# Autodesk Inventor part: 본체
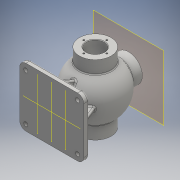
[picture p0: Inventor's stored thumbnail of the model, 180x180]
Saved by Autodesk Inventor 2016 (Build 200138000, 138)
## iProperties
Created: 2017-01
Part Number: 본체
Material: 일반
Document SubType Name: Modeling
Designer: Administrator
Density: 1 g/cm^3
Appearance: 기본값
Author: Administrator
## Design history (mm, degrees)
sketch "스케치1"
  geometry: L1 (0, 0)-(125, 0); L2 (125, 0)-(125, -115); L3 (125, -115)-(0, -115); L4 (0, -115)-(0, 0)
  constraints: 8 end point, 2 parallel, 1 horizontal, 1 perpendicular
  dimensions: "d0" = 115 distance of L1.end L2.end; "d1" = 125 distance of L2.end L3.end
extrude "돌출1" new body sketch "스케치1" distance "d2" = 10; taper "d3" = 0 deg
sketch "스케치2"
  geometry: L1 (-125, 0)-(-125, 115) reference; L2 (-125, 0)-(0, 0) reference; 1 further point
  dimensions: "d4" = 12 distance from line of L1 point (-113, 12); "d5" = 12 distance from line of L2 point (-113, 12)
hole "구멍1" sketch "스케치2" at (-113, 12) diameter "d6" = 8; stored, may be unused: countersink angle "d10" = 90 deg, drill point angle "d12" = 118 deg; dims "d7" = 6, "d8" = 12, "d9" = 3, "d11" = 8
fillet "모깎기1" dims "d19" = 12
node "작업 평면1"
sketch "스케치3"
  geometry: L1 (113.5, 116)-(113.5, 102.5); L2 (113.5, 85)-(-22.5, 85); L3 (-22.5, 102.5)-(-22.5, 116); L4 (91, 0)-(0, 0) reference; L5 (-12, 10)-(-12, 0) reference; L6 (-22.5, 116)-(2.512, 116); L7 (88.488, 116)-(113.5, 116); L8 (-6.5, 102.5)-(6.222, 102.5); L9 (-6.5, 102.5)-(-22.5, 102.5); L10 (113.5, 102.5)-(97.5, 102.5); L11 (97.5, 102.5)-(97.5, 103.5); L12 (97.5, 103.5)-(95.75, 103.5); L13 (95.75, 103.5)-(95.75, 102.5); L14 (95.75, 102.5)-(84.778, 102.5); A1 r 53 centre (45.5, 85) between (88.488, 116) and (2.512, 116); A2 r 43 centre (45.5, 85) between (84.778, 102.5) and (6.222, 102.5); 2 further points
  constraints: 24 end point, 7 perpendicular, 4 point on circle, 3 parallel, 2 centre point, 2 horizontal, 2 point on line, 1 midpoint, 1 vertical
  dimensions: "d22" = 136 distance of L3.end L1.start; "d23" = 85 distance between parallel lines of L4 L2; "d24" = 31 distance of L2.end L3.end; "d25" = 10.5 distance between parallel lines of L5 L3; "d26" = 53 radius of A1; "d28" = 43 radius of A2; "d36" = 17.5 distance between parallel lines of L2 L8; "d39" = 16 distance of L1.end L10.end; "d40" = 18.5 distance between parallel lines of L2 L12; "d41" = 17.5 distance between parallel lines of L2 L14; "d42" = 17.5 distance between parallel lines of L2 L10; "d43" = 1.75 distance of L11.end L12.end; "d44" = 136 distance between parallel lines of L3 L1; "d45" = 31 distance between parallel lines of L2 L6; "d46" = 68 distance of L2.end A1.centre
revolve "회전1" sketch "스케치3" stored, may be unused: angle "d32" = 90 deg
fillet "모깎기2" dims "d47" = 3
chamfer "모따기1" distance "d48" = 1; stored, may be unused: second distance "d49" = 2, angle "d50" = 45 deg
node "작업 평면2"
sketch "스케치4"
  geometry: L1 (-93.5, -125.5)-(-31.5, -125.5) reference; L2 (-125, -103)-(-125, -12) reference; C1 r 27 at (-62.5, -57.5); 1 further point
  constraints: 1 centre point
  dimensions: "d52" = 68 distance from line of C1.centre L1; "d53" = 62.5 distance from line of L2 C1.centre; "d54" = 54 diameter of C1
extrude "돌출2" join sketch "스케치4" stored distance "d55" = 10; taper "d56" = 0 deg
sketch "스케치5"
  geometry: C1 r 13 at (0, 0); 1 further point
  constraints: 1 centre point
  dimensions: "d57" = 26 diameter of C1
extrude "돌출3" cut sketch "스케치5" distance "d58" = 58; taper "d59" = 0 deg
fillet "모깎기3" dims "d60" = 3
chamfer "모따기2" distance "d61" = 1; stored, may be unused: second distance "d62" = 2, angle "d63" = 45 deg
sketch "스케치6" dims "d64" = 40
  geometry: 3 further points
  constraints: 1 horizontal alignment, 2 other
hole "구멍2" sketch "스케치6" at (-20, 0) diameter "d65" = 3.242; stored, may be unused: countersink angle "d69" = 90 deg, drill point angle "d71" = 118 deg; dims "d66" = 9, "d67" = 12, "d68" = 3, "d70" = 11
sketch "스케치7" dims "d75" = 48
  geometry: 3 further points
  constraints: 1 vertical alignment, 2 other
hole "구멍3" sketch "스케치7" at (0, 24) diameter "d76" = 3.242; stored, may be unused: countersink angle "d80" = 90 deg, drill point angle "d82" = 118 deg; dims "d77" = 16, "d78" = 12, "d79" = 3, "d81" = 19
sketch "스케치8" dims "d86" = 45
  geometry: 3 further points
  constraints: 1 vertical alignment, 2 other
hole "구멍4" sketch "스케치8" at (0, 22.5) diameter "d87" = 3.242; stored, may be unused: countersink angle "d91" = 90 deg, drill point angle "d93" = 118 deg; dims "d88" = 12, "d89" = 12, "d90" = 3, "d92" = 15
node "작업 평면3"
sketch "스케치11"
  geometry: L1 (101, 10)-(110, 10) reference; L2 (103, 10)-(86.485, 50.876); L3 (103, 10)-(-2, 10); L4 (101, 10)-(0, 10) reference; L5 (14.515, 50.876)-(-2, 10); L6 (-9, 10)-(0, 10) reference; L7 (113, 0)-(113, 7) reference; L8 (-12, 7)-(-12, 0) reference; A1 r 49.592 centre (50.5, 85) between (14.515, 50.876) and (86.485, 50.876)
  constraints: 6 end point, 2 point on circle, 2 point on line, 1 centre point
  dimensions: "d114" = 112 deg angle of L1 L2; "d115" = 112 deg angle of L6 L5; "d116" = 10 distance from line of L7 L2.start; "d117" = 10 distance from line of L8 L3.end
extrude "돌출5" join sketch "스케치11" stored distance "d118" = 8; taper "d119" = 0 deg
sketch "스케치12"
  geometry: L1 (79.219, 44.109)-(93, 10); L2 (91, 10)-(100, 10) reference; L3 (103, 7)-(103, 0) reference; A1 r 53 centre (45.5, 85) between (87.613, 117.179) and (87.613, 52.821) reference; 1 further point
  constraints: 2 end point, 1 point on circle
  dimensions: "d120" = 112 deg angle of L2 L1; "d121" = 0 distance from line of L2 L1.end; "d122" = 10 distance from line of L3 L1.end
feature "리브2" sketch "스케치12" dims "d123" = 1, "d124" = 8, "d125" = 0, "d126" = 0, "d127" = 1, "d128" = 1
fillet "모깎기4" dims "d129" = 3
fillet "모깎기5" dims "d130" = 3
node "작업 평면4"
node "작업 평면5"
sketch "스케치16"
  geometry: L1 (-145.589, -62.485)-(-145.589, -28.515); L2 (-145.589, -28.515)-(-134.411, -28.515); L3 (-134.411, -28.515)-(-134.411, -62.485); L4 (-134.411, -62.485)-(-145.589, -62.485); L5 (-150, -67.121)-(-150, -63.879) reference; L6 (-116, 22.5)-(-54, 22.5) reference; 3 further points
  constraints: 2 midpoint, 2 other
  dimensions: "d139" = 10 distance from line of L5 point (-140, -62.485); "d140" = 68 distance from line of L6 point (-145.589, -45.5)
feature "엠보싱3" sketch "스케치16" dims "d0" = 115, "d1" = 125, "d19" = 12, "d141" = 0.5, "d142" = 0
node "솔리드1"
pattern_linear "직사각형 패턴1" dims "d15" = 101, "d18" = 91
pattern_circular "원형 패턴1" dims angle "d73" = 360 deg
pattern_circular "원형 패턴2" dims angle "d84" = 360 deg
pattern_circular "원형 패턴3" dims angle "d95" = 360 deg
mirror "대칭1"
other parameters: "d20" = -62.5, "d21" = 106, "d97" = -57.5, "d133" = 27, "d138" = -27
